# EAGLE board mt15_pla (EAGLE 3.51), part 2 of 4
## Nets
GND: C1. C2. C3. C4. C5. C6. C7. C8. C9. C10. C11. C12. C13. C14. C15. C16. T1. T2. T3. T4. T5. T6. T7. T8. T9. T10. T11. T12. T13. T14. T15. T16. T27. T29. T30. T31. T32. T33. T34. T35. T36. T37. T38. T39. T40. T41. T42. T43. T53. T55. T56. T57. T58. T59. T60. T61. T62. T63. T64. T65. T66. T67. T68. T69. T79. T81. T82. T83. T84. T85. T86. T87. T88. T89. T90. T91. T92. T93. T94. T95. T105. T107. T108. T109. T110. T111. T112. T113. T114. T115. T116. T117. T118. T119. T120. T121. T131. T133. T134. T135. T136. T137. T138. T139. T140. T141. T142. T143. T144. T145. T146. T147. T157. T159. T160. T161. T162. T163. T164. T165. T166. T167. T168. T169. T170. T171. T172. T173. T183. T185. T186. T187. T188. T189. T190. T191. T192. T193. T194. T195. T196. T197. T198. T199. T209. T211. T212. T213. T214. T215. T216. T217. T218. T219. T220. T221. T222. T223. T224. T225. T235. T237. T238. T239. T240. T241. T242. T243. T244. T245. T246. T247. T248. T249. T250. T251. T261. T263. T264. T265. T266. T267. T268. T269. T270. T271. T272. T273. T274. T275. T276. T277. T287. T289. T290. T291. T292. T293. T294. T295. T296. T297. T298. T299. T300. T301. T302. T303. T313. T315. T316. T317. T318. T319. T320. T321. T322. T323. T324. T325. T326. T327. T328. T329. T339. T341. T342. T343. T344. T345. T346. T347. T348. T349. T350. T351. T352. T353. T354. T355. T365. T367. T368. T369. T370. T371. T372. T373. T374. T375. T376. T377. T378. T379. T380. T381. T391. T393. T394. T395. T396. T397. T398. T399. T400. T401. T402. T403. T404. T405. T406. T407.
I0: T1. T27. T53. T79. T105. T131. T157. T183. T209. T235. T261. T287. T313. T339. T365. T391.
I1: T2. T29. T55. T81. T107. T133. T159. T185. T211. T237. T263. T289. T315. T341. T367. T393.
I2: T3. T30. T56. T82. T108. T134. T160. T186. T212. T238. T264. T290. T316. T342. T368. T394.
I3: T4. T31. T57. T83. T109. T135. T161. T187. T213. T239. T265. T291. T317. T343. T369. T395.
I4: T5. T32. T58. T84. T110. T136. T162. T188. T214. T240. T266. T292. T318. T344. T370. T396.
I5: T6. T33. T59. T85. T111. T137. T163. T189. T215. T241. T267. T293. T319. T345. T371. T397.
I6: T7. T34. T60. T86. T112. T138. T164. T190. T216. T242. T268. T294. T320. T346. T372. T398.
I7: T8. T35. T61. T87. T113. T139. T165. T191. T217. T243. T269. T295. T321. T347. T373. T399.
I8: T9. T36. T62. T88. T114. T140. T166. T192. T218. T244. T270. T296. T322. T348. T374. T400.
I9: T10. T37. T63. T89. T115. T141. T167. T193. T219. T245. T271. T297. T323. T349. T375. T401.
I10: T11. T38. T64. T90. T116. T142. T168. T194. T220. T246. T272. T298. T324. T350. T376. T402.
I11: T12. T39. T65. T91. T117. T143. T169. T195. T221. T247. T273. T299. T325. T351. T377. T403.
I12: T13. T40. T66. T92. T118. T144. T170. T196. T222. T248. T274. T300. T326. T352. T378. T404.
I13: T14. T41. T67. T93. T119. T145. T171. T197. T223. T249. T275. T301. T327. T353. T379. T405.
I14: T15. T42. T68. T94. T120. T146. T172. T198. T224. T250. T276. T302. T328. T354. T380. T406.
I15: T16. T43. T69. T95. T121. T147. T173. T199. T225. T251. T277. T303. T329. T355. T381. T407.
N$1: J1. T1.
N$2: J2. T2.
N$3: J3. T3.
N$4: J1. J2. J3. J4. J5. J6. J7. J8. J9. J10. J11. J12. J13. J14. J15. J16. R3. T17. T18. T19. T20. T21. T22. T23. T24. T25. T26.
N$5: J16. T16.
N$6: J15. T15.
N$7: J14. T14.
N$8: J13. T13.
N$9: J12. T12.
N$10: J6. T6.
N$11: J5. T5.
N$12: J4. T4.
N$13: J7. T7.
N$14: J8. T8.
N$15: J9. T9.
N$16: J10. T10.
N$17: J11. T11.
N$18: J27. T27.
N$19: J28. T29.
N$20: J29. T30.
N$21: J27. J28. J29. J30. J31. J32. J33. J34. J35. J36. J37. J38. J39. J40. J41. J42. R1. T28. T44. T45. T46. T47. T48. T49. T50. T51. T52.
N$22: J42. T43.
N$23: J41. T42.
N$24: J26. T26.
N$25: J17. T17.
N$26: J18. T18.
N$27: J19. T19.
N$28: J20. T20.
N$29: J21. T21.
N$30: J22. T22.
N$31: J23. T23.
N$32: J24. T24.
N$33: J25. T25.
N$34: J40. T41.
N$35: J39. T40.
N$36: J38. T39.
N$37: J32. T33.
N$38: J31. T32.
N$39: J30. T31.
N$40: J33. T34.
N$41: J34. T35.
N$42: J35. T36.
N$43: J36. T37.
N$44: J37. T38.
N$45: J52. T52.
N$46: J43. T28.
N$47: J44. T44.
N$48: J45. T45.
N$49: J46. T46.
N$50: J47. T47.
N$51: J48. T48.
N$52: J49. T49.
N$53: J50. T50.
N$54: J51. T51.
N$55: J53. T53.
N$56: J54. T55.
N$57: J55. T56.
N$58: J53. J54. J55. J56. J57. J58. J59. J60. J61. J62. J63. J64. J65. J66. J67. J68. R2. T54. T70. T71. T72. T73. T74. T75. T76. T77. T78.
N$59: J68. T69.
N$60: J67. T68.
N$61: J66. T67.
N$62: J65. T66.
N$63: J64. T65.
N$64: J58. T59.
N$65: J57. T58.
N$66: J56. T57.
N$67: J59. T60.
N$68: J60. T61.
N$69: J61. T62.
N$70: J62. T63.
N$71: J63. T64.
N$72: J78. T78.
N$73: J69. T54.
N$74: J70. T70.
N$75: J71. T71.
N$76: J72. T72.
N$77: J73. T73.
N$78: J74. T74.
N$79: J75. T75.
N$80: J76. T76.
N$81: J77. T77.
N$82: J79. T79.
N$83: J80. T81.
N$84: J81. T82.
N$85: J79. J80. J81. J82. J83. J84. J85. J86. J87. J88. J89. J90. J91. J92. J93. J94. R4. T80. T96. T97. T98. T99. T100. T101. T102. T103. T104.
N$86: J94. T95.
N$87: J93. T94.
N$88: J92. T93.
N$89: J91. T92.
N$90: J90. T91.
N$91: J84. T85.
N$92: J83. T84.
N$93: J82. T83.
N$94: J85. T86.
N$95: J86. T87.
N$96: J87. T88.
N$97: J88. T89.
N$98: J89. T90.
N$99: J104. T104.
N$100: J95. T80.
N$101: J96. T96.
N$102: J97. T97.
N$103: J98. T98.
N$104: J99. T99.
N$105: J100. T100.
N$106: J101. T101.
N$107: J102. T102.
N$108: J103. T103.
N$109: J105. T105.
N$110: J106. T107.
N$111: J107. T108.
N$112: J105. J106. J107. J108. J109. J110. J111. J112. J113. J114. J115. J116. J117. J118. J119. J120. R5. T106. T122. T123. T124. T125. T126. T127. T128. T129. T130.
N$113: J120. T121.
N$114: J119. T120.
N$115: J118. T119.
N$116: J117. T118.
N$117: J116. T117.
N$118: J110. T111.
N$119: J109. T110.
N$120: J108. T109.
N$121: J111. T112.
N$122: J112. T113.
N$123: J113. T114.
N$124: J114. T115.
N$125: J115. T116.
N$126: J130. T130.
N$127: J121. T106.
N$128: J122. T122.
N$129: J123. T123.
N$130: J124. T124.
N$131: J125. T125.
N$132: J126. T126.
N$133: J127. T127.
N$134: J128. T128.
N$135: J129. T129.
N$136: J131. T131.
N$137: J132. T133.
N$138: J133. T134.
N$139: J131. J132. J133. J134. J135. J136. J137. J138. J139. J140. J141. J142. J143. J144. J145. J146. R6. T132. T148. T149. T150. T151. T152. T153. T154. T155. T156.
N$140: J146. T147.
N$141: J145. T146.
N$142: J144. T145.
N$143: J143. T144.
N$144: J142. T143.
N$145: J136. T137.
N$146: J135. T136.
N$147: J134. T135.
N$148: J137. T138.
N$149: J138. T139.
N$150: J139. T140.
N$151: J140. T141.
N$152: J141. T142.
N$153: J156. T156.
N$154: J147. T132.
N$155: J148. T148.
N$156: J149. T149.
N$157: J150. T150.
N$158: J151. T151.
N$159: J152. T152.
N$160: J153. T153.
N$161: J154. T154.
N$162: J155. T155.
N$163: J157. T157.
N$164: J158. T159.
N$165: J159. T160.
N$166: J157. J158. J159. J160. J161. J162. J163. J164. J165. J166. J167. J168. J169. J170. J171. J172. R7. T158. T174. T175. T176. T177. T178. T179. T180. T181. T182.
N$167: J172. T173.
N$168: J171. T172.
N$169: J170. T171.
N$170: J169. T170.
N$171: J168. T169.
N$172: J162. T163.
N$173: J161. T162.
N$174: J160. T161.
N$175: J163. T164.
N$176: J164. T165.
N$177: J165. T166.
N$178: J166. T167.
N$179: J167. T168.
N$180: J182. T182.
N$181: J173. T158.
N$182: J174. T174.
N$183: J175. T175.
N$184: J176. T176.
N$185: J177. T177.
N$186: J178. T178.
N$187: J179. T179.
N$188: J180. T180.
N$189: J181. T181.
N$190: J183. T183.
N$191: J184. T185.
N$192: J185. T186.
N$193: J183. J184. J185. J186. J187. J188. J189. J190. J191. J192. J193. J194. J195. J196. J197. J198. R8. T184. T200. T201. T202. T203. T204. T205. T206. T207. T208.
N$194: J198. T199.
N$195: J197. T198.
N$196: J196. T197.
N$197: J195. T196.
N$198: J194. T195.
N$199: J188. T189.
N$200: J187. T188.
N$201: J186. T187.
N$202: J189. T190.
N$203: J190. T191.
N$204: J191. T192.
N$205: J192. T193.
N$206: J193. T194.
N$207: J208. T208.
N$208: J199. T184.
N$209: J200. T200.
N$210: J201. T201.
N$211: J202. T202.
N$212: J203. T203.
N$213: J204. T204.
N$214: J205. T205.
N$215: J206. T206.
N$216: J207. T207.
N$217: J209. T209.
N$218: J210. T211.
N$219: J211. T212.
N$220: J209. J210. J211. J212. J213. J214. J215. J216. J217. J218. J219. J220. J221. J222. J223. J224. R9. T210. T226. T227. T228. T229. T230. T231. T232. T233. T234.
N$221: J224. T225.
N$222: J223. T224.
N$223: J222. T223.
N$224: J221. T222.
N$225: J220. T221.
N$226: J214. T215.
N$227: J213. T214.
N$228: J212. T213.
N$229: J215. T216.
N$230: J216. T217.
N$231: J217. T218.
N$232: J218. T219.
N$233: J219. T220.
N$234: J234. T234.
N$235: J225. T210.
N$236: J226. T226.
N$237: J227. T227.
N$238: J228. T228.
N$239: J229. T229.
N$240: J230. T230.
N$241: J231. T231.
N$242: J232. T232.
N$243: J233. T233.
N$244: J235. T235.
N$245: J236. T237.
N$246: J237. T238.
N$247: J235. J236. J237. J238. J239. J240. J241. J242. J243. J244. J245. J246. J247. J248. J249. J250. R10. T236. T252. T253. T254. T255. T256. T257. T258. T259. T260.
N$248: J250. T251.
N$249: J249. T250.
N$250: J248. T249.
N$251: J247. T248.
N$252: J246. T247.
N$253: J240. T241.
N$254: J239. T240.
N$255: J238. T239.
N$256: J241. T242.
N$257: J242. T243.
N$258: J243. T244.
N$259: J244. T245.
N$260: J245. T246.
N$261: J260. T260.
N$262: J251. T236.
N$263: J252. T252.
N$264: J253. T253.
N$265: J254. T254.
N$266: J255. T255.
N$267: J256. T256.
N$268: J257. T257.
N$269: J258. T258.
N$270: J259. T259.
N$271: J261. T261.
N$272: J262. T263.
N$273: J263. T264.
N$274: J261. J262. J263. J264. J265. J266. J267. J268. J269. J270. J271. J272. J273. J274. J275. J276. R11. T262. T278. T279. T280. T281. T282. T283. T284. T285. T286.
N$275: J276. T277.
N$276: J275. T276.
N$277: J274. T275.
N$278: J273. T274.
N$279: J272. T273.
N$280: J266. T267.
N$281: J265. T266.
N$282: J264. T265.
N$283: J267. T268.
N$284: J268. T269.
N$285: J269. T270.
N$286: J270. T271.
N$287: J271. T272.
N$288: J286. T286.
N$289: J277. T262.
N$290: J278. T278.
N$291: J279. T279.
N$292: J280. T280.
N$293: J281. T281.
N$294: J282. T282.
N$295: J283. T283.
N$296: J284. T284.
N$297: J285. T285.
N$298: J287. T287.
N$299: J288. T289.
N$300: J289. T290.
N$301: J287. J288. J289. J290. J291. J292. J293. J294. J295. J296. J297. J298. J299. J300. J301. J302. R12. T288. T304. T305. T306. T307. T308. T309. T310. T311. T312.
N$302: J302. T303.
N$303: J301. T302.
N$304: J300. T301.
N$305: J299. T300.
N$306: J298. T299.
N$307: J292. T293.
N$308: J291. T292.
N$309: J290. T291.
N$310: J293. T294.
N$311: J294. T295.
N$312: J295. T296.
N$313: J296. T297.
N$314: J297. T298.
N$315: J312. T312.
N$316: J303. T288.
N$317: J304. T304.
N$318: J305. T305.
N$319: J306. T306.
N$320: J307. T307.
N$321: J308. T308.
N$322: J309. T309.
N$323: J310. T310.
N$324: J311. T311.
N$325: J313. T313.
N$326: J314. T315.
N$327: J315. T316.
N$328: J313. J314. J315. J316. J317. J318. J319. J320. J321. J322. J323. J324. J325. J326. J327. J328. R13. T314. T330. T331. T332. T333. T334. T335. T336. T337. T338.
N$329: J328. T329.
N$330: J327. T328.
N$331: J326. T327.
N$332: J325. T326.
N$333: J324. T325.
N$334: J318. T319.
N$335: J317. T318.
N$336: J316. T317.
N$337: J319. T320.
N$338: J320. T321.
N$339: J321. T322.
N$340: J322. T323.
N$341: J323. T324.
N$342: J338. T338.
N$343: J329. T314.
N$344: J330. T330.
N$345: J331. T331.
N$346: J332. T332.
N$347: J333. T333.
N$348: J334. T334.
N$349: J335. T335.
N$350: J336. T336.
N$351: J337. T337.
N$352: J339. T339.
N$353: J340. T341.
N$354: J341. T342.
N$355: J339. J340. J341. J342. J343. J344. J345. J346. J347. J348. J349. J350. J351. J352. J353. J354. R14. T340. T356. T357. T358. T359. T360. T361. T362. T363. T364.
N$356: J354. T355.
N$357: J353. T354.
N$358: J352. T353.
N$359: J351. T352.
N$360: J350. T351.
N$361: J344. T345.
N$362: J343. T344.
N$363: J342. T343.
N$364: J345. T346.
N$365: J346. T347.
N$366: J347. T348.
N$367: J348. T349.
N$368: J349. T350.
N$369: J364. T364.
N$370: J355. T340.
N$371: J356. T356.
N$372: J357. T357.
N$373: J358. T358.
N$374: J359. T359.
N$375: J360. T360.
N$376: J361. T361.
N$377: J362. T362.
N$378: J363. T363.
N$379: J365. T365.
N$380: J366. T367.
N$381: J367. T368.
N$382: J365. J366. J367. J368. J369. J370. J371. J372. J373. J374. J375. J376. J377. J378. J379. J380. R15. T366. T382. T383. T384. T385. T386. T387. T388. T389. T390.
N$383: J380. T381.
N$384: J379. T380.
N$385: J378. T379.
N$386: J377. T378.
N$387: J376. T377.
N$388: J370. T371.
N$389: J369. T370.
N$390: J368. T369.
N$391: J371. T372.
N$392: J372. T373.
N$393: J373. T374.
N$394: J374. T375.
N$395: J375. T376.
N$396: J390. T390.
N$397: J381. T366.
N$398: J382. T382.
N$399: J383. T383.
N$400: J384. T384.
N$401: J385. T385.
N$402: J386. T386.
N$403: J387. T387.
N$404: J388. T388.
N$405: J389. T389.
N$406: J391. T391.
N$407: J392. T393.
N$408: J393. T394.
N$409: J391. J392. J393. J394. J395. J396. J397. J398. J399. J400. J401. J402. J403. J404. J405. J406. R16. T392. T408. T409. T410. T411. T412. T413. T414. T415. T416.
N$410: J406. T407.
N$411: J405. T406.
N$412: J404. T405.
N$413: J403. T404.
N$414: J402. T403.
N$415: J396. T397.
N$416: J395. T396.
N$417: J394. T395.
N$418: J397. T398.
N$419: J398. T399.
N$420: J399. T400.
N$421: J400. T401.
N$422: J401. T402.
N$423: J416. T416.
N$424: J407. T392.
N$425: J408. T408.
N$426: J409. T409.
N$427: J410. T410.
N$428: J411. T411.
N$429: J412. T412.
N$430: J413. T413.
N$431: J414. T414.
N$432: J415. T415.
Q0: J17. J43. J69. J95. J121. J147. J173. J199. J225. J251. J277. J303. J329. J355. J381. J407.
Q1: J18. J44. J70. J96. J122. J148. J174. J200. J226. J252. J278. J304. J330. J356. J382. J408.
Q2: J19. J45. J71. J97. J123. J149. J175. J201. J227. J253. J279. J305. J331. J357. J383. J409.
Q3: J20. J46. J72. J98. J124. J150. J176. J202. J228. J254. J280. J306. J332. J358. J384. J410.
Q4: J21. J47. J73. J99. J125. J151. J177. J203. J229. J255. J281. J307. J333. J359. J385. J411.
Q5: J22. J48. J74. J100. J126. J152. J178. J204. J230. J256. J282. J308. J334. J360. J386. J412.
Q6: J23. J49. J75. J101. J127. J153. J179. J205. J231. J257. J283. J309. J335. J361. J387. J413.
Q7: J24. J50. J76. J102. J128. J154. J180. J206. J232. J258. J284. J310. J336. J362. J388. J414.
Q8: J25. J51. J77. J103. J129. J155. J181. J207. J233. J259. J285. J311. J337. J363. J389. J415.
Q9: J26. J52. J78. J104. J130. J156. J182. J208. J234. J260. J286. J312. J338. J364. J390. J416.
VCC: C1. C2. C3. C4. C5. C6. C7. C8. C9. C10. C11. C12. C13. C14. C15. C16. R1. R2. R3. R4. R5. R6. R7. R8. R9. R10. R11. R12. R13. R14. R15. R16. T17. T18. T19. T20. T21. T22. T23. T24. T25. T26. T28. T44. T45. T46. T47. T48. T49. T50. T51. T52. T54. T70. T71. T72. T73. T74. T75. T76. T77. T78. T80. T96. T97. T98. T99. T100. T101. T102. T103. T104. T106. T122. T123. T124. T125. T126. T127. T128. T129. T130. T132. T148. T149. T150. T151. T152. T153. T154. T155. T156. T158. T174. T175. T176. T177. T178. T179. T180. T181. T182. T184. T200. T201. T202. T203. T204. T205. T206. T207. T208. T210. T226. T227. T228. T229. T230. T231. T232. T233. T234. T236. T252. T253. T254. T255. T256. T257. T258. T259. T260. T262. T278. T279. T280. T281. T282. T283. T284. T285. T286. T288. T304. T305. T306. T307. T308. T309. T310. T311. T312. T314. T330. T331. T332. T333. T334. T335. T336. T337. T338. T340. T356. T357. T358. T359. T360. T361. T362. T363. T364. T366. T382. T383. T384. T385. T386. T387. T388. T389. T390. T392. T408. T409. T410. T411. T412. T413. T414. T415. T416.

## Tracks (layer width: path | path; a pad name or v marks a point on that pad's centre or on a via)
GND  (via drill 0.61 pad 1.02, 2.54 pad 5.08)
  Top 0.406: T4. 18.41,8.66 18.41,8.89 v19.05,9.53 19.68,10.16 19.68,10.39 T32. | T5. 22.23,8.66 22.23,8.89 v22.86,9.53 23.5,10.16 23.5,10.39 T33. | T6. 26.04,8.66 26.04,8.89 v26.67,9.53 27.33,10.19 T34. | 15.88,10.39 T31. 15.9,10.19 v15.24,9.53 14.58,8.87 T3. | T1. 6.96,8.87 v7.62,9.53 8.28,10.19 T29. | T2. 10.77,8.87 v11.43,9.53 12.09,10.19 T30. | T27. 4.47,10.19 v3.81,9.53 | T16. 64.11,8.87 v64.77,9.53 | T15. 60.3,8.87 v60.96,9.53 61.62,10.19 T43. | T14. 56.49,8.87 v57.15,9.53 57.81,10.19 T42. | T41. 54,10.19 v53.34,9.53 52.68,8.87 T13. | T40. 50.19,10.19 v49.53,9.53 48.87,8.87 T12. | T39. 46.38,10.19 v45.72,9.53 45.06,8.87 T11. | T38. 42.57,10.19 v41.91,9.53 41.25,8.87 T10. | T7. 29.82,8.87 v30.48,9.53 31.14,10.19 T35. | T8. 33.63,8.87 v34.29,9.53 34.95,10.19 T36. | T9. 37.44,8.87 v38.1,9.53 38.76,10.19 T37. | T79. 4.47,18.44 v3.81,17.78 | T81. 8.28,18.44 v7.62,17.78 6.96,17.12 T53. | T55. 10.77,17.12 v11.43,17.78 12.09,18.44 T82. | T56. 14.58,17.12 v15.24,17.78 15.9,18.44 T83. | T57. 18.39,17.12 v19.05,17.78 19.71,18.44 T84. | T58. 22.2,17.12 v22.86,17.78 23.52,18.44 T85. | T59. 26.01,17.12 v26.67,17.78 27.33,18.44 T86. | T60. 29.82,17.12 v30.48,17.78 31.14,18.44 T87. | T61. 33.63,17.12 v34.29,17.78 34.95,18.44 T88. | T62. 37.44,17.12 v38.1,17.78 38.76,18.44 T89. | T63. 41.25,17.12 v41.91,17.78 42.57,18.44 T90. | T64. 45.06,17.12 v45.72,17.78 46.38,18.44 T91. | T65. 48.87,17.12 v49.53,17.78 50.19,18.44 T92. | T66. 52.68,17.12 v53.34,17.78 54,18.44 T93. | T67. 56.49,17.12 v57.15,17.78 57.81,18.44 T94. | T68. 60.3,17.12 v60.96,17.78 61.62,18.44 T95. | T69. 64.11,17.12 v64.77,17.78 | T131. 4.47,26.7 v3.81,26.04
  Top 0.406: T133. 8.28,26.7 v7.62,26.04 6.96,25.38 T105. | T134. 12.09,26.7 v11.43,26.04 10.77,25.38 T107. | T135. 15.9,26.7 v15.24,26.04 14.58,25.38 T108. | T136. 19.71,26.7 v19.05,26.04 18.39,25.38 T109. | T137. 23.52,26.7 v22.86,26.04 22.2,25.38 T110. | T138. 27.33,26.7 v26.67,26.04 26.01,25.38 T111. | T139. 31.14,26.7 v30.48,26.04 29.82,25.38 T112. | T140. 34.95,26.7 v34.29,26.04 33.63,25.38 T113. | T141. 38.76,26.7 v38.1,26.04 37.44,25.38 T114. | T142. 42.57,26.7 v41.91,26.04 41.25,25.38 T115. | T143. 46.38,26.7 v45.72,26.04 45.06,25.38 T116. | T144. 50.19,26.7 v49.53,26.04 48.87,25.38 T117. | T145. 54,26.7 v53.34,26.04 52.68,25.38 T118. | T146. 57.81,26.7 v57.15,26.04 56.49,25.38 T119. | T147. 61.62,26.7 v60.96,26.04 60.3,25.38 T120. | T121. 64.11,25.38 v64.77,26.04 | T183. 4.47,34.95 v3.81,34.29 | T235. 4.47,43.2 v3.81,42.55 | T287. 4.47,51.46 v3.81,50.8 | T157. 6.96,33.63 v7.62,34.29 8.28,34.95 T185. | T159. 10.77,33.63 v11.43,34.29 12.09,34.95 T186. | T160. 14.58,33.63 v15.24,34.29 15.9,34.95 T187. | T161. 18.39,33.63 v19.05,34.29 19.71,34.95 T188. | T162. 22.2,33.63 v22.86,34.29 23.52,34.95 T189. | T190. 27.33,34.95 v26.67,34.29 26.01,33.63 T163. | T164. 29.82,33.63 v30.48,34.29 31.14,34.95 T191. | T165. 33.63,33.63 v34.29,34.29 34.95,34.95 T192. | T166. 37.44,33.63 v38.1,34.29 38.76,34.95 T193. | T167. 41.25,33.63 v41.91,34.29 42.57,34.95 T194. | T168. 45.06,33.63 v45.72,34.29 46.38,34.95 T195. | T169. 48.87,33.63 v49.53,34.29 50.19,34.95 T196. | T170. 52.68,33.63 v53.34,34.29 54,34.95 T197. | T171. 56.49,33.63 v57.15,34.29 57.81,34.95 T198. | T172. 60.3,33.63 v60.96,34.29 61.62,34.95 T199.
  Top 0.406: T173. 64.11,33.63 v64.77,34.29 | T391. 4.47,67.97 v3.81,67.31 | T339. 4.47,59.72 v3.81,59.05 | T209. 6.96,41.88 v7.62,42.55 8.28,43.2 T237. | T261. 6.96,50.14 v7.62,50.8 8.28,51.46 T289. | T263. 10.77,50.14 v11.43,50.8 12.09,51.46 T290. | T264. 14.58,50.14 v15.24,50.8 15.9,51.46 T291. | T265. 18.39,50.14 v19.05,50.8 19.71,51.46 T292. | T266. 22.2,50.14 v22.86,50.8 23.52,51.46 T293. | T267. 26.01,50.14 v26.67,50.8 27.33,51.46 T294. | T268. 29.82,50.14 v30.48,50.8 31.14,51.46 T295. | T269. 33.63,50.14 v34.29,50.8 34.95,51.46 T296. | T270. 37.44,50.14 v38.1,50.8 38.76,51.46 T297. | T271. 41.25,50.14 v41.91,50.8 42.57,51.46 T298. | T272. 45.06,50.14 v45.72,50.8 46.38,51.46 T299. | T273. 48.87,50.14 v49.53,50.8 50.19,51.46 T300. | T274. 52.68,50.14 v53.34,50.8 54,51.46 T301. | T275. 56.49,50.14 v57.15,50.8 57.81,51.46 T302. | T276. 60.3,50.14 v60.96,50.8 61.62,51.46 T303. | T277. 64.11,50.14 v64.77,50.8 | T225. 64.11,41.88 v64.77,42.55 | T211. 10.77,41.88 v11.43,42.55 12.09,43.2 T238. | T212. 14.58,41.88 v15.24,42.55 15.9,43.2 T239. | T213. 18.39,41.88 v19.05,42.55 19.71,43.2 T240. | T214. 22.2,41.88 v22.86,42.55 23.52,43.2 T241. | T215. 26.01,41.88 v26.67,42.55 27.33,43.2 T242. | T216. 29.82,41.88 v30.48,42.55 31.14,43.2 T243. | T217. 33.63,41.88 v34.29,42.55 34.95,43.2 T244. | T218. 37.44,41.88 v38.1,42.55 38.76,43.2 T245. | T219. 41.25,41.88 v41.91,42.55 42.57,43.2 T246. | T220. 45.06,41.88 v45.72,42.55 46.38,43.2 T247. | T221. 48.87,41.88 v49.53,42.55 50.19,43.2 T248. | T222. 52.68,41.88 v53.34,42.55 54,43.2 T249. | T223. 56.49,41.88 v57.15,42.55 57.81,43.2 T250. | T224. 60.3,41.88 v60.96,42.55 61.62,43.2 T251.
  Top 0.406: T313. 6.96,58.4 v7.62,59.05 8.28,59.72 T341. | T365. 6.96,66.65 v7.62,67.31 8.28,67.97 T393. | T367. 10.77,66.65 v11.43,67.31 12.09,67.97 T394. | T368. 14.58,66.65 v15.24,67.31 15.9,67.97 T395. | T369. 18.39,66.65 v19.05,67.31 19.71,67.97 T396. | T315. 10.77,58.4 v11.43,59.05 12.09,59.72 T342. | T316. 14.58,58.4 v15.24,59.05 15.9,59.72 T343. | T317. 18.39,58.4 v19.05,59.05 19.71,59.72 T344. | T318. 22.2,58.4 v22.86,59.05 23.52,59.72 T345. | T319. 26.01,58.4 v26.67,59.05 27.33,59.72 T346. | T320. 29.82,58.4 v30.48,59.05 31.14,59.72 T347. | T321. 33.63,58.4 v34.29,59.05 34.95,59.72 T348. | T370. 22.2,66.65 v22.86,67.31 23.52,67.97 T397. | T371. 26.01,66.65 v26.67,67.31 27.33,67.97 T398. | T372. 29.82,66.65 v30.48,67.31 31.14,67.97 T399. | T373. 33.63,66.65 v34.29,67.31 34.95,67.97 T400. | T374. 37.44,66.65 v38.1,67.31 38.76,67.97 T401. | T375. 41.25,66.65 v41.91,67.31 42.57,67.97 T402. | T376. 45.06,66.65 v45.72,67.31 46.38,67.97 T403. | T377. 48.87,66.65 v49.53,67.31 50.19,67.97 T404. | T378. 52.68,66.65 v53.34,67.31 54,67.97 T405. | T379. 56.49,66.65 v57.15,67.31 57.81,67.97 T406. | T380. 60.3,66.65 v60.96,67.31 61.62,67.97 T407. | T381. 64.11,66.65 v64.77,67.31 | T322. 37.44,58.4 v38.1,59.05 38.76,59.72 T349. | T323. 41.25,58.4 v41.91,59.05 42.57,59.72 T350. | T324. 45.06,58.4 v45.72,59.05 46.38,59.72 T351. | T325. 48.87,58.4 v49.53,59.05 50.19,59.72 T352. | T326. 52.68,58.4 v53.34,59.05 54,59.72 T353. | T327. 56.49,58.4 v57.15,59.05 57.81,59.72 T354. | T328. 60.3,58.4 v60.96,59.05 61.62,59.72 T355. | T329. 64.11,58.4 v64.77,59.05
  Top 0.813: C2. 64.77,12.06 v64.77,9.53 67.94,9.53 C1. | C4. 64.77,20.32 v64.77,17.78 67.94,17.78 C3. | C6. 64.77,28.57 v64.77,26.04 67.94,26.04 C5. | C8. 64.77,36.83 v64.77,34.29 67.94,34.29 C7. | C10. 64.77,45.09 v64.77,42.55 67.94,42.55 C9. | C12. 64.77,53.34 v64.77,50.8 67.94,50.8 C11. | C14. 64.77,61.59 v64.77,59.05 67.94,59.05 C13. | C16. 64.77,69.85 v64.77,67.31 67.94,67.31 C15.
  Top 1.27: 2.54,9.53 v3.81,9.53 | 2.54,9.53 1.27,9.53 1.27,17.78 | 1.27,17.78 v3.81,17.78 | 1.27,17.78 1.27,26.04 | 1.27,26.04 v3.81,26.04 | 1.27,26.04 1.27,34.29 | 1.27,34.29 v3.81,34.29 | 1.27,34.29 1.27,42.55 | 1.27,42.55 v3.81,42.55 | 1.27,42.55 1.27,50.8 | 1.27,50.8 v3.81,50.8 | 1.27,50.8 1.27,59.05 | 1.27,59.05 v3.81,59.05 | 1.27,59.05 1.27,67.31 v3.81,67.31 | 2.54,9.53 v2.54,4.13 4.76,1.91 v5.08,1.91 v7.62,1.91 8.26,1.27 v10.16,1.27
  Bottom 0.813: 1.27,67.31 1.27,72.39 v3.81,74.93 6.67,77.79 109.22,77.79 v112.08,74.93
  Bottom 1.27: v64.77,9.53 v60.96,9.53 v57.15,9.53 v53.34,9.53 v49.53,9.53 v45.72,9.53 v41.91,9.53 v38.1,9.53 v34.29,9.53 v30.48,9.53 v26.67,9.53 v22.86,9.53 v19.05,9.53 v15.24,9.53 v11.43,9.53 v7.62,9.53 v3.81,9.53 2.54,9.53 | 2.54,9.53 1.27,9.53 1.27,17.78 | 1.27,17.78 v3.81,17.78 v7.62,17.78 v11.43,17.78 v15.24,17.78 v19.05,17.78 v22.86,17.78 v26.67,17.78 v30.48,17.78 v34.29,17.78 v38.1,17.78 v41.91,17.78 v45.72,17.78 v49.53,17.78 v53.34,17.78 v57.15,17.78 v60.96,17.78 v64.77,17.78 | 1.27,17.78 1.27,26.04 | 1.27,26.04 v3.81,26.04 v7.62,26.04 v11.43,26.04 v15.24,26.04 v19.05,26.04 v22.86,26.04 v26.67,26.04 v30.48,26.04 v34.29,26.04 v38.1,26.04 v41.91,26.04 v45.72,26.04 v49.53,26.04 v53.34,26.04 v57.15,26.04 v60.96,26.04 v64.77,26.04 | 1.27,26.04 1.27,34.29 | 1.27,34.29 v3.81,34.29 v7.62,34.29 v11.43,34.29 v15.24,34.29 v19.05,34.29 v22.86,34.29 v26.67,34.29 v30.48,34.29 v34.29,34.29 v38.1,34.29 v41.91,34.29 v45.72,34.29 v49.53,34.29 v53.34,34.29 v57.15,34.29 v60.96,34.29 v64.77,34.29 | 1.27,34.29 1.27,42.55 | 1.27,42.55 v3.81,42.55 v7.62,42.55 v11.43,42.55 v15.24,42.55 v19.05,42.55 v22.86,42.55 v26.67,42.55 v30.48,42.55 v34.29,42.55 v38.1,42.55 v41.91,42.55 v45.72,42.55 v49.53,42.55 v53.34,42.55 v57.15,42.55 v60.96,42.55 v64.77,42.55 | 1.27,42.55 1.27,50.8 | 1.27,50.8 v3.81,50.8 v7.62,50.8 v11.43,50.8 v15.24,50.8 v19.05,50.8 v22.86,50.8 v26.67,50.8 v30.48,50.8 v34.29,50.8 v38.1,50.8 v41.91,50.8 v45.72,50.8 v49.53,50.8 v53.34,50.8 v57.15,50.8 v60.96,50.8 v64.77,50.8 | 1.27,50.8 1.27,59.05 | 1.27,59.05 1.27,67.31 v3.81,67.31 v7.62,67.31 v11.43,67.31 v15.24,67.31 v19.05,67.31 v22.86,67.31 v26.67,67.31 v30.48,67.31 v34.29,67.31 v38.1,67.31 v41.91,67.31 v45.72,67.31 v49.53,67.31 v53.34,67.31 v57.15,67.31 v60.96,67.31 v64.77,67.31
  Bottom 1.27: 1.27,59.05 v3.81,59.05 v7.62,59.05 v11.43,59.05 v15.24,59.05 v19.05,59.05 v22.86,59.05 v26.67,59.05 v30.48,59.05 v34.29,59.05 v38.1,59.05 v41.91,59.05 v45.72,59.05 v49.53,59.05 v53.34,59.05 v57.15,59.05 v60.96,59.05 v64.77,59.05 | v2.54,4.13 2.54,0.95 | v2.54,4.13 2.54,9.53 | 5.08,4.13 v5.08,1.91 5.08,0.95 | v2.54,4.13 5.08,4.13 | 7.62,4.13 v7.62,1.91 7.62,0.95 | 5.08,4.13 7.62,4.13 | 10.16,4.13 v10.16,1.27 10.16,0.95 | 7.62,4.13 10.16,4.13 | 12.7,0.95 12.7,4.13 10.16,4.13
  pour Bottom (isolate 0.356): 0.32,0.64 0.32,78.42 115.57,78.42 115.57,72.07 2.86,72.07 1.91,71.12 1.91,69.22 3.81,67.31 4.76,67.31 4.76,63.82 2.86,63.82 1.91,62.87 1.91,60.96 3.81,59.05 4.76,59.05 4.76,55.56 2.86,55.56 1.91,54.61 1.91,52.7 3.81,50.8 4.76,50.8 4.76,47.31 2.86,47.31 1.91,46.35 1.91,44.45 3.81,42.55 4.76,42.55 4.76,39.05 2.86,39.05 1.91,38.1 1.91,36.2 3.81,34.29 4.76,34.29 4.76,30.8 2.86,30.8 1.91,29.84 1.91,27.94 3.81,26.04 4.76,26.04 4.76,22.54 2.86,22.54 1.91,21.59 1.91,19.68 3.81,17.78 4.76,17.78 4.76,14.29 2.86,14.29 1.91,13.34 1.91,11.43 3.81,9.53 4.76,9.53 4.76,4.13 2.54,4.13 2.54,0.64
  pour Top (isolate 0.356): 0.32,0.64 0.32,78.42 62.23,78.42 62.23,72.07 2.86,72.07 1.91,71.12 1.91,69.22 4.45,66.67 4.45,63.82 2.86,63.82 1.91,62.87 1.91,60.96 4.45,58.42 4.45,55.56 2.86,55.56 1.91,54.61 1.91,52.7 4.45,50.16 4.45,47.31 2.86,47.31 1.91,46.35 1.91,44.45 4.45,41.91 4.45,39.05 2.86,39.05 1.91,38.1 1.91,36.2 4.45,33.66 4.45,30.8 2.86,30.8 1.91,29.84 1.91,27.94 4.45,25.4 4.45,22.54 2.86,22.54 1.91,21.59 1.91,19.68 4.45,17.14 4.45,14.29 2.86,14.29 1.91,13.34 1.91,11.43 4.45,8.89 4.45,4.45 5.71,3.17 8.26,3.17 9.53,1.91 10.79,1.91 12.06,0.64
  pour Top (isolate 0.356): 71.12,78.42 71.12,72.07 115.25,72.07 115.25,78.42
I0  (via drill 0.61 pad 1.02)
  Top 0.406: 5.99,6.6 5.71,6.6 5.71,6.67 | 5.71,6.67 5.71,12.45 | 5.71,12.45 5.44,12.45 | 5.44,70.23 5.71,70.23 5.71,64.14 | 5.71,14.61 5.71,20.95 | 5.71,20.95 5.71,22.86 | 5.71,22.86 5.71,29.21 | 5.71,29.21 5.71,31.11 | 5.71,31.11 5.71,37.47 | 5.71,37.47 5.71,39.37 | 5.71,39.37 5.71,45.72 | 5.71,45.72 5.71,47.62 | 5.71,47.62 5.71,53.98 | 5.71,53.98 5.71,55.88 | 5.71,55.88 5.71,62.23 | 5.71,62.23 5.71,64.14 | 5.71,12.45 5.71,14.61 | 5.99,14.86 5.71,14.86 5.71,14.61 | 5.99,23.11 5.71,23.11 5.71,22.86 | 5.44,20.7 5.71,20.7 5.71,20.95 | 5.44,28.96 5.71,28.96 5.71,29.21 | 5.99,31.37 5.71,31.37 5.71,31.11 | 5.44,37.21 5.71,37.21 5.71,37.47 | 5.99,39.62 5.71,39.62 5.71,39.37 | 5.44,45.47 5.71,45.47 5.71,45.72 | 5.99,47.88 5.71,47.88 5.71,47.62 | 5.44,53.72 5.71,53.72 5.71,53.98 | 5.99,56.13 5.71,56.13 5.71,55.88 | 5.44,61.98 5.71,61.98 5.71,62.23 | 5.99,64.39 5.71,64.39 5.71,64.14 | 5.71,6.67 5.71,5.4 6.67,4.45 8.57,4.45 9.84,3.17 11.75,3.17 13.02,1.91 v15.24,1.91
  Bottom 1.27: 15.24,0.95 v15.24,1.91 15.24,4.13
I1  (via drill 0.61 pad 1.02)
  Top 0.406: 9.8,6.6 9.53,6.6 9.53,6.67 | 9.53,6.67 9.53,12.45 | 9.53,12.45 9.25,12.45 | 9.25,70.23 9.53,70.23 9.53,64.14 | 9.53,14.61 9.53,20.95 | 9.53,20.95 9.53,22.86 | 9.53,22.86 9.53,29.21 | 9.53,29.21 9.53,31.11 | 9.53,31.11 9.53,37.47 | 9.53,37.47 9.53,39.37 | 9.53,39.37 9.53,45.72 | 9.53,45.72 9.53,47.62 | 9.53,47.62 9.53,53.98 | 9.53,53.98 9.53,55.88 | 9.53,55.88 9.53,62.23 | 9.53,62.23 9.53,64.14 | 9.53,12.45 9.53,14.61 | 9.8,14.86 9.53,14.86 9.53,14.61 | 9.25,20.7 9.53,20.7 9.53,20.95 | 9.8,23.11 9.53,23.11 9.53,22.86 | 9.25,28.96 9.53,28.96 9.53,29.21 | 9.8,31.37 9.53,31.37 9.53,31.11 | 9.25,37.21 9.53,37.21 9.53,37.47 | 9.8,39.62 9.53,39.62 9.53,39.37 | 9.25,45.47 9.53,45.47 9.53,45.72 | 9.8,47.88 9.53,47.88 9.53,47.62 | 9.8,64.39 9.53,64.39 9.53,64.14 | 9.25,61.98 9.53,61.98 9.53,62.23 | 9.8,56.13 9.53,56.13 9.53,55.88 | 9.25,53.72 9.53,53.72 9.53,53.98 | 9.53,6.67 9.53,5.4 10.48,4.45 12.38,4.45 13.65,3.17 16.51,3.17 v17.78,1.91
  Bottom 1.27: 17.78,0.95 v17.78,1.91 17.78,4.13
I2  (via drill 0.61 pad 1.02)
  Top 0.406: 13.61,6.6 13.34,6.6 13.34,6.67 | 13.34,6.67 13.34,12.45 | 13.34,12.45 13.06,12.45 | 13.06,70.23 13.34,70.23 13.34,64.14 | 13.34,14.61 13.34,20.95 | 13.34,20.95 13.34,22.86 | 13.34,22.86 13.34,29.21 | 13.34,29.21 13.34,31.11 | 13.34,31.11 13.34,37.47 | 13.34,37.47 13.34,39.37 | 13.34,39.37 13.34,45.72 | 13.34,45.72 13.34,47.62 | 13.34,47.62 13.34,53.98 | 13.34,53.98 13.34,55.88 | 13.34,55.88 13.34,62.23 | 13.34,62.23 13.34,64.14 | 13.34,12.45 13.34,14.61 | 13.61,14.86 13.34,14.86 13.34,14.61 | 13.06,20.7 13.34,20.7 13.34,20.95 | 13.61,23.11 13.34,23.11 13.34,22.86 | 13.06,28.96 13.34,28.96 13.34,29.21 | 13.61,31.37 13.34,31.37 13.34,31.11 | 13.06,37.21 13.34,37.21 13.34,37.47 | 13.61,39.62 13.34,39.62 13.34,39.37 | 13.06,45.47 13.34,45.47 13.34,45.72 | 13.61,47.88 13.34,47.88 13.34,47.62 | 13.06,53.72 13.34,53.72 13.34,53.98 | 13.61,56.13 13.34,56.13 13.34,55.88 | 13.06,61.98 13.34,61.98 13.34,62.23 | 13.61,64.39 13.34,64.39 13.34,64.14 | 13.34,6.67 13.34,5.4 14.29,4.45 17.14,4.45 18.1,3.49 18.73,3.49 v20.32,1.91
  Bottom 1.27: 20.32,0.95 v20.32,1.91 20.32,4.13
I3  (via drill 0.61 pad 1.02)
  Top 0.406: 17.42,6.6 17.14,6.6 17.14,6.67 | 17.14,6.67 17.14,12.45 | 17.14,12.45 16.87,12.45 | 16.87,70.23 17.14,70.23 17.14,64.14 | 17.14,12.45 17.14,14.61 | 17.14,14.61 17.14,20.95 | 17.14,20.95 17.14,22.86 | 17.14,22.86 17.14,29.21 | 17.14,29.21 17.14,31.11 | 17.14,31.11 17.14,37.47 | 17.14,37.47 17.14,39.37 | 17.14,39.37 17.14,45.72 | 17.14,45.72 17.14,47.62 | 17.14,47.62 17.14,53.98 | 17.14,53.98 17.14,55.88 | 17.14,55.88 17.14,62.23 | 17.14,62.23 17.14,64.14 | 17.42,14.86 17.14,14.86 17.14,14.61 | 16.87,20.7 17.14,20.7 17.14,20.95 | 17.42,23.11 17.14,23.11 17.14,22.86 | 16.87,28.96 17.14,28.96 17.14,29.21 | 17.42,31.37 17.14,31.37 17.14,31.11 | 16.87,37.21 17.14,37.21 17.14,37.47 | 17.42,39.62 17.14,39.62 17.14,39.37 | 16.87,45.47 17.14,45.47 17.14,45.72 | 17.42,47.88 17.14,47.88 17.14,47.62 | 17.42,64.39 17.14,64.39 17.14,64.14 | 16.87,61.98 17.14,61.98 17.14,62.23 | 17.42,56.13 17.14,56.13 17.14,55.88 | 16.87,53.72 17.14,53.72 17.14,53.98 | 17.14,6.67 17.14,6.03 18.41,4.76 20,4.76 v22.86,1.91
  Bottom 1.27: 22.86,0.95 v22.86,1.91 22.86,4.13
I4  (via drill 0.61 pad 1.02)
  Top 0.406: 21.23,6.6 20.95,6.6 20.95,6.67 | 20.95,6.67 20.95,12.45 | 20.95,12.45 20.68,12.45 | 20.68,70.23 20.95,70.23 20.95,64.14 | 20.95,12.45 20.95,14.61 | 20.95,14.61 20.95,20.95 | 20.95,20.95 20.95,22.86 | 20.95,22.86 20.95,29.21 | 20.95,29.21 20.95,31.11 | 20.95,31.11 20.95,37.47 | 20.95,37.47 20.95,39.37 | 20.95,39.37 20.95,45.72 | 20.95,45.72 20.95,47.62 | 20.95,47.62 20.95,53.98 | 20.95,53.98 20.95,55.88 | 20.95,55.88 20.95,62.23 | 20.95,62.23 20.95,64.14 | 21.23,14.86 20.95,14.86 20.95,14.61 | 20.68,20.7 20.95,20.7 20.95,20.95 | 21.23,23.11 20.95,23.11 20.95,22.86 | 20.68,28.96 20.95,28.96 20.95,29.21 | 21.23,31.37 20.95,31.37 20.95,31.11 | 21.23,47.88 20.95,47.88 20.95,47.62 | 20.68,45.47 20.95,45.47 20.95,45.72 | 20.68,37.21 20.95,37.21 20.95,37.47 | 21.23,39.62 20.95,39.62 20.95,39.37 | 20.68,53.72 20.95,53.72 20.95,53.98 | 21.23,56.13 20.95,56.13 20.95,55.88 | 20.68,61.98 20.95,61.98 20.95,62.23 | 21.23,64.39 20.95,64.39 20.95,64.14 | 20.95,6.67 20.95,5.71 23.5,3.17 v25.4,3.17
  Bottom 1.27: 25.4,0.95 v25.4,3.17 25.4,4.13
I5  (via drill 0.61 pad 1.02)
  Top 0.406: 25.04,6.6 24.77,6.6 24.77,6.67 | 24.77,6.67 24.77,12.45 | 24.77,12.45 24.49,12.45 | 24.49,70.23 24.77,70.23 24.77,64.14 | 24.77,12.45 24.77,14.61 | 24.77,14.61 24.77,20.95 | 24.77,20.95 24.77,22.86 | 24.77,22.86 24.77,29.21 | 24.77,29.21 24.77,31.11 | 24.77,31.11 24.77,37.47 | 24.77,37.47 24.77,39.37 | 24.77,39.37 24.77,45.72 | 24.77,45.72 24.77,47.62 | 24.77,47.62 24.77,53.98 | 24.77,53.98 24.77,55.88 | 24.77,55.88 24.77,62.23 | 24.77,62.23 24.77,64.14 | 25.04,14.86 24.77,14.86 24.77,14.61 | 24.49,20.7 24.77,20.7 24.77,20.95 | 25.04,23.11 24.77,23.11 24.77,22.86 | 25.04,31.37 24.77,31.37 24.77,31.11 | 24.49,28.96 24.77,28.96 24.77,29.21 | 24.49,37.21 24.77,37.21 24.77,37.47 | 25.04,39.62 24.77,39.62 24.77,39.37 | 24.49,45.47 24.77,45.47 24.77,45.72 | 25.04,47.88 24.77,47.88 24.77,47.62 | 24.49,53.72 24.77,53.72 24.77,53.98 | 25.04,56.13 24.77,56.13 24.77,55.88 | 24.49,61.98 24.77,61.98 24.77,62.23 | 25.04,64.39 24.77,64.39 24.77,64.14 | 24.77,6.67 24.77,5.4 25.4,4.76 26.99,4.76 v27.94,3.81
  Bottom 1.27: 27.94,0.95 v27.94,3.81 27.94,4.13
I6  (via drill 0.61 pad 1.02)
  Top 0.406: 28.85,6.6 28.57,6.6 28.57,6.67 | 28.57,6.67 28.57,12.45 | 28.57,12.45 28.3,12.45 | 28.3,70.23 28.57,70.23 28.57,64.14 | 28.57,12.45 28.57,14.61 | 28.57,14.61 28.57,20.95 | 28.57,20.95 28.57,22.86 | 28.57,22.86 28.57,29.21 | 28.57,29.21 28.57,31.11 | 28.57,31.11 28.57,37.47 | 28.57,37.47 28.57,39.37 | 28.57,39.37 28.57,45.72 | 28.57,45.72 28.57,47.62 | 28.57,47.62 28.57,53.98 | 28.57,53.98 28.57,55.88 | 28.57,55.88 28.57,62.23 | 28.57,62.23 28.57,64.14 | 28.3,20.7 28.57,20.7 28.57,20.95 | 28.85,23.11 28.57,23.11 28.57,22.86 | 28.3,28.96 28.57,28.96 28.57,29.21 | 28.85,31.37 28.57,31.37 28.57,31.11 | 28.85,47.88 28.57,47.88 28.57,47.62 | 28.3,45.47 28.57,45.47 28.57,45.72 | 28.85,39.62 28.57,39.62 28.57,39.37 | 28.3,37.21 28.57,37.21 28.57,37.47 | 28.85,64.39 28.57,64.39 28.57,64.14 | 28.3,61.98 28.57,61.98 28.57,62.23 | 28.85,56.13 28.57,56.13 28.57,55.88 | 28.3,53.72 28.57,53.72 28.57,53.98 | 28.85,14.86 28.57,14.86 28.57,14.61 | 28.57,6.67 28.57,5.71 v30.48,3.81
  Bottom 1.27: 30.48,4.13 v30.48,3.81 30.48,0.95
I7  (via drill 0.61 pad 1.02)
  Top 0.406: 32.66,6.6 32.38,6.6 32.38,6.67 | 32.38,6.67 32.38,12.45 | 32.38,12.45 32.11,12.45 | 32.11,70.23 32.38,70.23 32.38,64.14 | 32.38,12.45 32.38,14.61 | 32.38,14.61 32.38,20.95 | 32.38,20.95 32.38,22.86 | 32.38,22.86 32.38,29.21 | 32.38,29.21 32.38,31.11 | 32.38,31.11 32.38,37.47 | 32.38,37.47 32.38,39.37 | 32.38,39.37 32.38,45.72 | 32.38,45.72 32.38,47.62 | 32.38,47.62 32.38,53.98 | 32.38,53.98 32.38,55.88 | 32.38,55.88 32.38,62.23 | 32.38,62.23 32.38,64.14 | 32.66,14.86 32.38,14.86 32.38,14.61 | 32.11,20.7 32.38,20.7 32.38,20.95 | 32.66,23.11 32.38,23.11 32.38,22.86 | 32.11,28.96 32.38,28.96 32.38,29.21 | 32.66,31.37 32.38,31.37 32.38,31.11 | 32.11,37.21 32.38,37.21 32.38,37.47 | 32.66,39.62 32.38,39.62 32.38,39.37 | 32.66,47.88 32.38,47.88 32.38,47.62 | 32.11,45.47 32.38,45.47 32.38,45.72 | 32.11,53.72 32.38,53.72 32.38,53.98 | 32.66,56.13 32.38,56.13 32.38,55.88 | 32.11,61.98 32.38,61.98 32.38,62.23 | 32.66,64.39 32.38,64.39 32.38,64.14 | 32.38,6.67 32.38,4.45 v33.02,3.81
  Bottom 1.27: 33.02,0.95 v33.02,3.81 33.02,4.13
I8  (via drill 0.61 pad 1.02)
  Top 0.406: 36.47,6.6 36.2,6.6 36.2,6.67 | 36.2,6.67 36.2,12.45 | 36.2,12.45 35.92,12.45 | 35.92,70.23 36.2,70.23 36.2,64.14 | 36.2,12.45 36.2,14.61 | 36.2,14.61 36.2,20.95 | 36.2,20.95 36.2,22.86 | 36.2,22.86 36.2,29.21 | 36.2,29.21 36.2,31.11 | 36.2,31.11 36.2,37.47 | 36.2,37.47 36.2,39.37 | 36.2,39.37 36.2,45.72 | 36.2,45.72 36.2,47.62 | 36.2,47.62 36.2,53.98 | 36.2,53.98 36.2,55.88 | 36.2,55.88 36.2,62.23 | 36.2,62.23 36.2,64.14 | 36.47,14.86 36.2,14.86 36.2,14.61 | 35.92,20.7 36.2,20.7 36.2,20.95 | 36.47,23.11 36.2,23.11 36.2,22.86 | 35.92,28.96 36.2,28.96 36.2,29.21 | 36.47,31.37 36.2,31.37 36.2,31.11 | 35.92,37.21 36.2,37.21 36.2,37.47 | 36.47,39.62 36.2,39.62 36.2,39.37 | 35.92,45.47 36.2,45.47 36.2,45.72 | 36.47,47.88 36.2,47.88 36.2,47.62 | 35.92,53.72 36.2,53.72 36.2,53.98 | 36.47,56.13 36.2,56.13 36.2,55.88 | 35.92,61.98 36.2,61.98 36.2,62.23 | 36.47,64.39 36.2,64.39 36.2,64.14 | 36.2,6.67 36.2,4.45 v35.56,3.81
  Bottom 1.27: 35.56,0.95 v35.56,3.81 35.56,4.13
I9  (via drill 0.61 pad 1.02)
  Top 0.406: 40.28,6.6 40.01,6.6 40.01,6.67 | 40.01,12.45 39.73,12.45 | 40.01,6.67 40.01,12.45 | 39.73,70.23 40.01,70.23 40.01,64.14 | 40.01,12.45 40.01,14.61 | 40.01,14.61 40.01,20.95 | 40.01,20.95 40.01,22.86 | 40.01,22.86 40.01,29.21 | 40.01,29.21 40.01,31.11 | 40.01,31.11 40.01,37.47 | 40.01,37.47 40.01,39.37 | 40.01,39.37 40.01,45.72 | 40.01,45.72 40.01,47.62 | 40.01,47.62 40.01,53.98 | 40.01,53.98 40.01,55.88 | 40.01,55.88 40.01,62.23 | 40.01,62.23 40.01,64.14 | 40.28,14.86 40.01,14.86 40.01,14.61 | 39.73,20.7 40.01,20.7 40.01,20.95 | 40.28,23.11 40.01,23.11 40.01,22.86 | 39.73,28.96 40.01,28.96 40.01,29.21 | 40.28,31.37 40.01,31.37 40.01,31.11 | 39.73,37.21 40.01,37.21 40.01,37.47 | 40.28,39.62 40.01,39.62 40.01,39.37 | 39.73,45.47 40.01,45.47 40.01,45.72 | 40.28,47.88 40.01,47.88 40.01,47.62 | 39.73,53.72 40.01,53.72 40.01,53.98 | 40.28,56.13 40.01,56.13 40.01,55.88 | 39.73,61.98 40.01,61.98 40.01,62.23 | 40.28,64.39 40.01,64.39 40.01,64.14 | 40.01,6.67 40.01,5.71 v38.1,3.81
  Bottom 1.27: 38.1,0.95 v38.1,3.81 38.1,4.13
I10  (via drill 0.61 pad 1.02)
  Top 0.406: 44.09,6.6 43.81,6.6 43.81,6.67 | 43.81,6.67 43.81,12.45 | 43.81,12.45 43.54,12.45 | 43.54,70.23 43.81,70.23 43.81,64.14 | 43.81,12.45 43.81,14.61 | 43.81,14.61 43.81,20.95 | 43.81,20.95 43.81,22.86 | 43.81,22.86 43.81,29.21 | 43.81,29.21 43.81,31.11 | 43.81,31.11 43.81,37.47 | 43.81,37.47 43.81,39.37 | 43.81,39.37 43.81,45.72 | 43.81,45.72 43.81,47.62 | 43.81,47.62 43.81,53.98 | 43.81,53.98 43.81,55.88 | 43.81,55.88 43.81,62.23 | 43.81,62.23 43.81,64.14 | 44.09,14.86 43.81,14.86 43.81,14.61 | 43.54,20.7 43.81,20.7 43.81,20.95 | 44.09,23.11 43.81,23.11 43.81,22.86 | 43.54,28.96 43.81,28.96 43.81,29.21 | 44.09,31.37 43.81,31.37 43.81,31.11 | 43.54,37.21 43.81,37.21 43.81,37.47 | 44.09,39.62 43.81,39.62 43.81,39.37 | 43.54,45.47 43.81,45.47 43.81,45.72 | 44.09,47.88 43.81,47.88 43.81,47.62 | 43.54,53.72 43.81,53.72 43.81,53.98 | 44.09,56.13 43.81,56.13 43.81,55.88 | 43.54,61.98 43.81,61.98 43.81,62.23 | 44.09,64.39 43.81,64.39 43.81,64.14 | 43.81,6.67 43.81,5.71 42.86,4.76 41.59,4.76 v40.64,3.81
  Bottom 1.27: 40.64,0.95 v40.64,3.81 40.64,4.13
I11  (via drill 0.61 pad 1.02)
  Top 0.406: 47.9,6.6 47.62,6.6 47.62,6.67 | 47.62,6.67 47.62,12.45 | 47.62,12.45 47.35,12.45 | 47.35,70.23 47.62,70.23 47.62,64.14 | 47.62,12.45 47.62,14.61 | 47.62,14.61 47.62,20.95 | 47.62,20.95 47.62,22.86 | 47.62,22.86 47.62,29.21 | 47.62,29.21 47.62,31.11 | 47.62,31.11 47.62,37.47 | 47.62,37.47 47.62,39.37 | 47.62,39.37 47.62,45.72 | 47.62,45.72 47.62,47.62 | 47.62,47.62 47.62,53.98 | 47.62,53.98 47.62,55.88 | 47.62,55.88 47.62,62.23 | 47.62,62.23 47.62,64.14 | 47.9,14.86 47.62,14.86 47.62,14.61 | 47.35,20.7 47.62,20.7 47.62,20.95 | 47.9,23.11 47.62,23.11 47.62,22.86 | 47.35,28.96 47.62,28.96 47.62,29.21 | 47.9,31.37 47.62,31.37 47.62,31.11 | 47.35,37.21 47.62,37.21 47.62,37.47 | 47.9,39.62 47.62,39.62 47.62,39.37 | 47.35,45.47 47.62,45.47 47.62,45.72 | 47.9,47.88 47.62,47.88 47.62,47.62 | 47.35,53.72 47.62,53.72 47.62,53.98 | 47.9,56.13 47.62,56.13 47.62,55.88 | 47.35,61.98 47.62,61.98 47.62,62.23 | 47.9,64.39 47.62,64.39 47.62,64.14 | 47.62,6.67 47.62,5.71 46.67,4.76 44.45,4.76 v43.18,3.49
  Bottom 1.27: 43.18,0.95 v43.18,3.49 43.18,4.13
I12  (via drill 0.61 pad 1.02)
  Top 0.406: 51.71,6.6 51.44,6.6 51.44,6.67 | 51.44,6.67 51.44,12.45 | 51.44,12.45 51.16,12.45 | 51.16,70.23 51.44,70.23 51.44,64.14 | 51.44,37.47 51.44,39.37 | 51.44,39.37 51.44,45.72 | 51.44,45.72 51.44,47.62 | 51.44,47.62 51.44,53.98 | 51.44,53.98 51.44,55.88 | 51.44,55.88 51.44,62.23 | 51.44,62.23 51.44,64.14 | 51.44,12.45 51.44,14.61 | 51.44,14.61 51.44,20.95 | 51.44,20.95 51.44,22.86 | 51.44,22.86 51.44,29.21 | 51.44,29.21 51.44,31.11 | 51.44,31.11 51.44,37.47 | 51.71,14.86 51.44,14.86 51.44,14.61 | 51.16,20.7 51.44,20.7 51.44,20.95 | 51.71,23.11 51.44,23.11 51.44,22.86 | 51.16,28.96 51.44,28.96 51.44,29.21 | 51.71,31.37 51.44,31.37 51.44,31.11 | 51.16,37.21 51.44,37.21 51.44,37.47 | 51.71,39.62 51.44,39.62 51.44,39.37 | 51.16,45.47 51.44,45.47 51.44,45.72 | 51.71,47.88 51.44,47.88 51.44,47.62 | 51.16,53.72 51.44,53.72 51.44,53.98 | 51.71,56.13 51.44,56.13 51.44,55.88 | 51.16,61.98 51.44,61.98 51.44,62.23 | 51.71,64.39 51.44,64.39 51.44,64.14 | 51.44,6.67 51.44,6.03 50.16,4.76 48.58,4.76 47.31,3.49 v45.72,3.49
  Bottom 1.27: 45.72,0.95 v45.72,3.49 45.72,4.13
I13  (via drill 0.61 pad 1.02)
  Top 0.406: 55.52,6.6 55.24,6.6 55.24,6.67 | 55.24,6.67 55.24,12.45 | 55.24,12.45 54.97,12.45 | 54.97,70.23 55.24,70.23 55.24,64.14 | 55.24,37.47 55.24,39.37 | 55.24,39.37 55.24,45.72 | 55.24,45.72 55.24,47.62 | 55.24,47.62 55.24,53.98 | 55.24,53.98 55.24,55.88 | 55.24,55.88 55.24,62.23 | 55.24,62.23 55.24,64.14 | 55.24,12.45 55.24,14.61 | 55.24,14.61 55.24,20.95 | 55.24,20.95 55.24,22.86 | 55.24,22.86 55.24,29.21 | 55.24,29.21 55.24,31.11 | 55.24,31.11 55.24,37.47 | 55.52,14.86 55.24,14.86 55.24,14.61 | 54.97,20.7 55.24,20.7 55.24,20.95 | 55.52,23.11 55.24,23.11 55.24,22.86 | 54.97,28.96 55.24,28.96 55.24,29.21 | 55.52,31.37 55.24,31.37 55.24,31.11 | 54.97,37.21 55.24,37.21 55.24,37.47 | 55.52,39.62 55.24,39.62 55.24,39.37 | 54.97,45.47 55.24,45.47 55.24,45.72 | 55.52,47.88 55.24,47.88 55.24,47.62 | 55.52,56.13 55.24,56.13 55.24,55.88 | 54.97,53.72 55.24,53.72 55.24,53.98 | 54.97,61.98 55.24,61.98 55.24,62.23 | 55.52,64.39 55.24,64.39 55.24,64.14 | 55.24,6.67 55.24,5.71 54.61,5.08 52.39,5.08 50.8,3.49 49.21,3.49 v48.26,2.54
  Bottom 1.27: 48.26,0.95 v48.26,2.54 48.26,4.13
I14  (via drill 0.61 pad 1.02)
  Top 0.406: 59.33,6.6 59.05,6.6 59.05,6.67 | 59.05,6.67 59.05,12.45 | 59.05,12.45 58.78,12.45 | 58.78,70.23 59.05,70.23 59.05,64.14 | 59.05,37.47 59.05,39.37 | 59.05,39.37 59.05,45.72 | 59.05,45.72 59.05,47.62 | 59.05,47.62 59.05,53.98 | 59.05,53.98 59.05,55.88 | 59.05,55.88 59.05,62.23 | 59.05,62.23 59.05,64.14 | 59.05,12.45 59.05,14.61 | 59.05,14.61 59.05,20.95 | 59.05,20.95 59.05,22.86 | 59.05,22.86 59.05,29.21 | 59.05,29.21 59.05,31.11 | 59.05,31.11 59.05,37.47 | 59.33,14.86 59.05,14.86 59.05,14.61 | 58.78,20.7 59.05,20.7 59.05,20.95 | 59.33,23.11 59.05,23.11 59.05,22.86 | 58.78,28.96 59.05,28.96 59.05,29.21 | 59.33,31.37 59.05,31.37 59.05,31.11 | 58.78,37.21 59.05,37.21 59.05,37.47 | 59.33,39.62 59.05,39.62 59.05,39.37 | 58.78,45.47 59.05,45.47 59.05,45.72 | 59.33,47.88 59.05,47.88 59.05,47.62 | 58.78,53.72 59.05,53.72 59.05,53.98 | 59.33,56.13 59.05,56.13 59.05,55.88 | 58.78,61.98 59.05,61.98 59.05,62.23 | 59.33,64.39 59.05,64.39 59.05,64.14 | 59.05,6.67 59.05,5.71 58.42,5.08 56.52,5.08 55.24,3.81 53.02,3.81 51.44,2.22 v50.8,2.22
  Bottom 1.27: 50.8,0.95 v50.8,2.22 50.8,4.13
I15  (via drill 0.61 pad 1.02)
  Top 0.406: 63.14,6.6 62.87,6.6 62.87,6.67 | 62.87,12.45 62.59,12.45 | 62.87,6.67 62.87,12.45 | 62.59,70.23 62.87,70.23 62.87,64.14 | 62.87,37.47 62.87,39.37 | 62.87,39.37 62.87,45.72 | 62.87,45.72 62.87,47.62 | 62.87,47.62 62.87,53.98 | 62.87,53.98 62.87,55.88 | 62.87,55.88 62.87,62.23 | 62.87,62.23 62.87,64.14 | 62.87,12.45 62.87,14.61 | 62.87,14.61 62.87,20.95 | 62.87,20.95 62.87,22.86 | 62.87,22.86 62.87,29.21 | 62.87,29.21 62.87,31.11 | 62.87,31.11 62.87,37.47 | 63.14,14.86 62.87,14.86 62.87,14.61 | 62.59,20.7 62.87,20.7 62.87,20.95 | 63.14,23.11 62.87,23.11 62.87,22.86 | 62.59,28.96 62.87,28.96 62.87,29.21 | 63.14,31.37 62.87,31.37 62.87,31.11 | 62.59,37.21 62.87,37.21 62.87,37.47 | 63.14,39.62 62.87,39.62 62.87,39.37 | 62.59,45.47 62.87,45.47 62.87,45.72 | 63.14,47.88 62.87,47.88 62.87,47.62 | 62.59,53.72 62.87,53.72 62.87,53.98 | 63.14,56.13 62.87,56.13 62.87,55.88 | 62.59,61.98 62.87,61.98 62.87,62.23 | 63.14,64.39 62.87,64.39 62.87,64.14 | 62.87,6.67 62.87,5.71 62.23,5.08 60.33,5.08 59.05,3.81 57.15,3.81 55.56,2.22 v53.34,2.22
  Bottom 1.27: 53.34,0.95 v53.34,2.22 53.34,4.13
N$1  (via drill 0.61 pad 1.02)
  Top 0.406: 7.92,6.6 7.92,6.66 v8.26,6.99
  Bottom 0.406: J1. 7.94,6.67 v8.26,6.99
N$2  (via drill 0.61 pad 1.02)
  Top 0.406: 11.73,6.6 11.73,6.66 v12.06,6.99
  Bottom 0.406: J2. 11.75,6.67 v12.06,6.99
N$3  (via drill 0.61 pad 1.02)
  Top 0.406: 15.54,6.6 15.54,6.66 v15.88,6.99
  Bottom 0.406: J3. 15.56,6.67 v15.88,6.99
N$4  (via drill 0.61 pad 1.02)
  Top 0.305: 71.4,6.6 71.44,6.57 71.44,5.4 71.75,5.4 | 71.75,5.4 75.25,5.4 | 75.25,5.4 79.06,5.4 | 75.21,6.6 75.25,6.57 75.25,5.4 | 79.02,6.6 79.06,6.57 79.06,5.4 | v70.17,5.4 71.75,5.4 | 110.11,6.35 109.16,5.4 105.73,5.4 | 79.06,5.4 82.87,5.4 | 82.87,5.4 86.68,5.4 | 86.68,5.4 90.49,5.4 | 90.49,5.4 94.3,5.4 | 94.3,5.4 98.11,5.4 | 98.11,5.4 101.92,5.4 | 101.92,5.4 105.73,5.4 | 82.83,6.6 82.87,6.6 82.87,5.4 | 86.64,6.6 86.68,6.6 86.68,5.4 | 90.45,6.6 90.49,6.6 90.49,5.4 | 94.26,6.6 94.3,6.6 94.3,5.4 | 98.07,6.6 98.11,6.6 98.11,5.4 | 101.88,6.6 101.92,6.6 101.92,5.4 | 105.69,6.6 105.73,6.6 105.73,5.4
  Bottom 0.305: 6.22,6.67 6.35,6.67 6.35,8.26 10.16,8.26 | 10.16,8.26 13.97,8.26 | 13.97,8.26 17.78,8.26 | 17.78,8.26 21.59,8.26 | 21.59,8.26 25.4,8.26 | 25.4,8.26 29.21,8.26 | 29.21,8.26 33.02,8.26 | 33.02,8.26 36.83,8.26 | 36.83,8.26 40.64,8.26 | 40.64,8.26 44.45,8.26 | 44.45,8.26 48.26,8.26 | 48.26,8.26 52.07,8.26 | 52.07,8.26 55.88,8.26 | 55.88,8.26 59.69,8.26 | 59.69,8.26 63.5,8.26 | 10.03,6.67 10.16,6.67 10.16,8.26 | 13.84,6.67 13.97,6.67 13.97,8.26 | 17.65,6.67 17.78,6.67 17.78,8.26 | 21.46,6.67 21.59,6.67 21.59,8.26 | 25.27,6.67 25.4,6.67 25.4,8.26 | 29.08,6.67 29.21,6.67 29.21,8.26 | 32.89,6.67 33.02,6.67 33.02,8.26 | 36.7,6.67 36.83,6.67 36.83,8.26 | 40.51,6.67 40.64,6.67 40.64,8.26 | 44.32,6.67 44.45,6.67 44.45,8.26 | 48.13,6.67 48.26,6.67 48.26,8.26 | 63.37,6.67 63.5,6.67 63.5,8.26 | 59.56,6.67 59.69,6.67 59.69,8.26 | 55.75,6.67 55.88,6.67 55.88,8.26 | 51.94,6.67 52.07,6.67 52.07,8.26 | 63.5,8.26 67.31,8.26 v70.17,5.4
N$5  (via drill 0.61 pad 1.02)
  Top 0.406: 65.08,6.6 65.08,6.66 v65.41,6.99
  Bottom 0.406: J16. 65.09,6.67 v65.41,6.99
N$6  (via drill 0.61 pad 1.02)
  Top 0.406: 61.27,6.6 61.27,6.66 v61.59,6.99
  Bottom 0.406: J15. 61.28,6.67 v61.59,6.99
N$7  (via drill 0.61 pad 1.02)
  Top 0.406: 57.45,6.6 57.45,6.66 v57.78,6.99
  Bottom 0.406: J14. 57.47,6.67 v57.78,6.99
N$8  (via drill 0.61 pad 1.02)
  Top 0.406: 53.65,6.6 53.65,6.66 v53.98,6.99
  Bottom 0.406: J13. 53.66,6.67 v53.98,6.99
N$9  (via drill 0.61 pad 1.02)
  Top 0.406: 49.84,6.6 49.84,6.66 v50.16,6.99
  Bottom 0.406: J12. 49.85,6.67 v50.16,6.99
N$10  (via drill 0.61 pad 1.02)
  Top 0.406: 26.98,6.6 26.98,6.66 v27.3,6.99
  Bottom 0.406: J6. 26.99,6.67 v27.3,6.99
N$11  (via drill 0.61 pad 1.02)
  Top 0.406: 23.16,6.6 23.16,6.66 v23.5,6.99
  Bottom 0.406: J5. 23.18,6.67 v23.5,6.99
N$12  (via drill 0.61 pad 1.02)
  Top 0.406: 19.36,6.6 19.36,6.66 v19.68,6.99
  Bottom 0.406: J4. 19.37,6.67 v19.68,6.99
N$13  (via drill 0.61 pad 1.02)
  Top 0.406: 30.79,6.6 30.79,6.66 v31.11,6.99
  Bottom 0.406: J7. 30.8,6.67 v31.11,6.99
N$14  (via drill 0.61 pad 1.02)
  Top 0.406: 34.59,6.6 34.59,6.66 v34.92,6.99
  Bottom 0.406: J8. 34.61,6.67 v34.92,6.99
N$15  (via drill 0.61 pad 1.02)
  Top 0.406: 38.41,6.6 38.41,6.66 v38.73,6.99
  Bottom 0.406: J9. 38.42,6.67 v38.73,6.99
N$16  (via drill 0.61 pad 1.02)
  Top 0.406: 42.22,6.6 42.22,6.66 v42.55,6.99
  Bottom 0.406: J10. 42.23,6.67 v42.55,6.99
N$17  (via drill 0.61 pad 1.02)
  Top 0.406: 46.02,6.6 46.02,6.66 v46.35,6.99
  Bottom 0.406: J11. 46.04,6.67 v46.35,6.99
N$18  (via drill 0.61 pad 1.02)
  Top 0.406: 3.5,12.45 3.5,12.39 v3.17,12.06
  Bottom 0.406: J27. 3.49,12.38 v3.17,12.06
N$19  (via drill 0.61 pad 1.02)
  Top 0.406: 7.32,12.45 7.32,12.39 v6.99,12.06
  Bottom 0.406: J28. 7.3,12.38 v6.99,12.06
N$20  (via drill 0.61 pad 1.02)
  Top 0.406: 11.12,12.45 11.12,12.39 v10.79,12.06
  Bottom 0.406: J29. 11.11,12.38 v10.79,12.06
N$21  (via drill 0.61 pad 1.02)
  Top 0.305: 73.38,11.81 73.34,11.85 73.34,13.02 73.66,13.02 | 73.66,13.02 77.15,13.02 | 77.15,13.02 80.96,13.02 | 77.19,11.81 77.15,11.85 77.15,13.02 | 81,11.81 80.96,11.85 80.96,13.02 | v70.17,13.02 73.66,13.02 | 110.11,12.06 109.16,13.02 107.63,13.02 | 80.96,13.02 84.77,13.02 | 84.77,13.02 88.58,13.02 | 88.58,13.02 92.39,13.02 | 92.39,13.02 96.2,13.02 | 96.2,13.02 100.01,13.02 | 100.01,13.02 103.82,13.02 | 103.82,13.02 107.63,13.02 | 107.67,11.81 107.63,11.81 107.63,13.02 | 103.86,11.81 103.82,11.81 103.82,13.02 | 100.05,11.81 100.01,11.81 100.01,13.02 | 96.24,11.81 96.2,11.81 96.2,13.02 | 92.43,11.81 92.39,11.81 92.39,13.02 | 84.81,11.81 84.77,11.81 84.77,13.02 | 88.62,11.81 88.58,11.81 88.58,13.02
  Bottom 0.305: 5.21,12.38 5.08,12.38 5.08,10.79 8.89,10.79 | 8.89,10.79 12.7,10.79 | 12.7,10.79 16.51,10.79 | 16.51,10.79 20.32,10.79 | 20.32,10.79 24.13,10.79 | 24.13,10.79 27.94,10.79 | 27.94,10.79 31.75,10.79 | 31.75,10.79 35.56,10.79 | 35.56,10.79 39.37,10.79 | 39.37,10.79 43.18,10.79 | 43.18,10.79 46.99,10.79 | 46.99,10.79 50.8,10.79 | 50.8,10.79 54.61,10.79 | 54.61,10.79 58.42,10.79 | 58.42,10.79 62.23,10.79 | 9.02,12.38 8.89,12.38 8.89,10.79 | 12.83,12.38 12.7,12.38 12.7,10.79 | 16.64,12.38 16.51,12.38 16.51,10.79 | 20.45,12.38 20.32,12.38 20.32,10.79 | 24.26,12.38 24.13,12.38 24.13,10.79 | 28.07,12.38 27.94,12.38 27.94,10.79 | 62.36,12.38 62.23,12.38 62.23,10.79 | 58.55,12.38 58.42,12.38 58.42,10.79 | 54.74,12.38 54.61,12.38 54.61,10.79 | 50.93,12.38 50.8,12.38 50.8,10.79 | 47.12,12.38 46.99,12.38 46.99,10.79 | 43.31,12.38 43.18,12.38 43.18,10.79 | 39.5,12.38 39.37,12.38 39.37,10.79 | 31.88,12.38 31.75,12.38 31.75,10.79 | 35.69,12.38 35.56,12.38 35.56,10.79 | 62.23,10.79 67.94,10.79 v70.17,13.02
  Bottom 0.406: 9.02,12.38 8.89,12.26
N$22  (via drill 0.61 pad 1.02)
  Top 0.406: 60.66,12.45 60.66,12.39 v60.33,12.06
  Bottom 0.406: J42. 60.64,12.38 v60.33,12.06
N$23  (via drill 0.61 pad 1.02)
  Top 0.406: 56.84,12.45 56.84,12.39 v56.52,12.06
  Bottom 0.406: J41. 56.83,12.38 v56.52,12.06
